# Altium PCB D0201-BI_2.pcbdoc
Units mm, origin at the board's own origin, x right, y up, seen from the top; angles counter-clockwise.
Board outline 13.9 x 13.3 mm, 2 copper layers (Top Layer, Bottom Layer), stack 0 mm thick; 1 components, 0 nets, 2 pads, 0 vias.
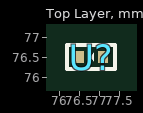
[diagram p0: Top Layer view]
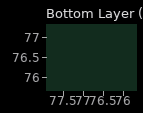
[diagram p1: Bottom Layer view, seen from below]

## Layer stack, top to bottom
Top Layer: signal copper (thickness not stored)
Bottom Layer: signal copper (thickness not stored)

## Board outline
83.75,69.85 69.85,69.85 69.85,83.15 83.75,83.15

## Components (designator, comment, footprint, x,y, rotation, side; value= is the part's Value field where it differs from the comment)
U? "" D0201-BI_2 76.8,76.5 r0 top

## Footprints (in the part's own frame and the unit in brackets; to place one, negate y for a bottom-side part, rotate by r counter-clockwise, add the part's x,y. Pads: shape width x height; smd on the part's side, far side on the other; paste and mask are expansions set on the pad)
D0201-BI_2 [mm]
  rect 0.25x0.3 smd: 1(-0.3,0) 2(0.3,0)
  silkscreen extent -0.6,-0.3 0.6,0.3

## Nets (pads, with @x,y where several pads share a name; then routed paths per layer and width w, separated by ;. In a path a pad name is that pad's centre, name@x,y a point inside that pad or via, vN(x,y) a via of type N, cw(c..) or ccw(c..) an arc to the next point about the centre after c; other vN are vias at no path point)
pads on no net: U?.1 U?.2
